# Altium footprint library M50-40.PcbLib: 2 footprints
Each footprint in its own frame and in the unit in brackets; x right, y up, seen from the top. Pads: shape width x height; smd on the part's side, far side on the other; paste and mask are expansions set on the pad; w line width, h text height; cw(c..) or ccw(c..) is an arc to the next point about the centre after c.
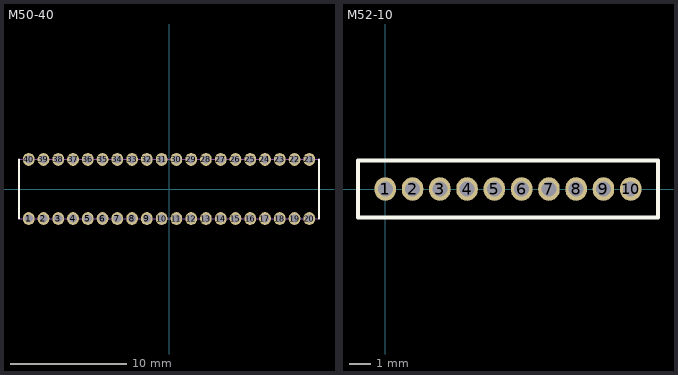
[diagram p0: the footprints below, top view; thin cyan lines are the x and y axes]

## M50-40 [mm] "M50 Series Female Header Connector"
height 4
pads (40):
  oval 1x1.1 hole 0.7: 1(-12.065,-2.54) 2(-10.795,-2.54) 3(-9.525,-2.54) 4(-8.255,-2.54) 5(-6.985,-2.54) 6(-5.715,-2.54) 7(-4.445,-2.54) 8(-3.175,-2.54) 9(-1.905,-2.54) 10(-0.635,-2.54) 11(0.635,-2.54) 12(1.905,-2.54) 13(3.175,-2.54) 14(4.445,-2.54) 15(5.715,-2.54) 16(6.985,-2.54) 17(8.255,-2.54) 18(9.525,-2.54) 19(10.795,-2.54) 20(12.065,-2.54) 21(12.065,2.54) 22(10.795,2.54) 23(9.525,2.54) 24(8.255,2.54) 25(6.985,2.54) 26(5.715,2.54) 27(4.445,2.54) 28(3.175,2.54) 29(1.905,2.54) 30(0.635,2.54) 31(-0.635,2.54) 32(-1.905,2.54) 33(-3.175,2.54) 34(-4.445,2.54) 35(-5.715,2.54) 36(-6.985,2.54) 37(-8.255,2.54) 38(-9.525,2.54) 39(-10.795,2.54) 40(-12.065,2.54)
Top Overlay:
  lines w0.203: -12.9,-2.54 -12.9,2.54 ; 12.9,-2.54 12.9,2.54
Mechanical 31:
  lines w0.102: -12.9,-2.54 -12.9,2.54 12.9,2.54 12.9,-2.54 -12.9,-2.54
  text ".Designator" at -4.445,0 h0.76
3D body: height 4, standoff 0.2, extent -12.9,-2.54 12.9,2.54

## M52-10 [mm] "M52 Series Connector 10 Pin"
height 4.6
pads (10):
  oval 1x1.1 hole 0.7: 1(0,0) 2(1.27,0) 3(2.54,0) 4(3.81,0) 5(5.08,0) 6(6.35,0) 7(7.62,0) 8(8.89,0) 9(10.16,0) 10(11.43,0)
Top Overlay:
  lines w0.203: -1.27,-1.325 0,-1.325 12.7,-1.325 12.7,1.325 -1.27,1.325 -1.27,-1.325
Mechanical 31:
  lines w0.102: -1.27,-1.325 -1.27,1.325 12.7,1.325 12.7,-1.325 -1.27,-1.325
3D body "2.17 10 pin header.step": height 4.3, standoff -1.48, extent -0.635,-0.635 12.065,0.615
